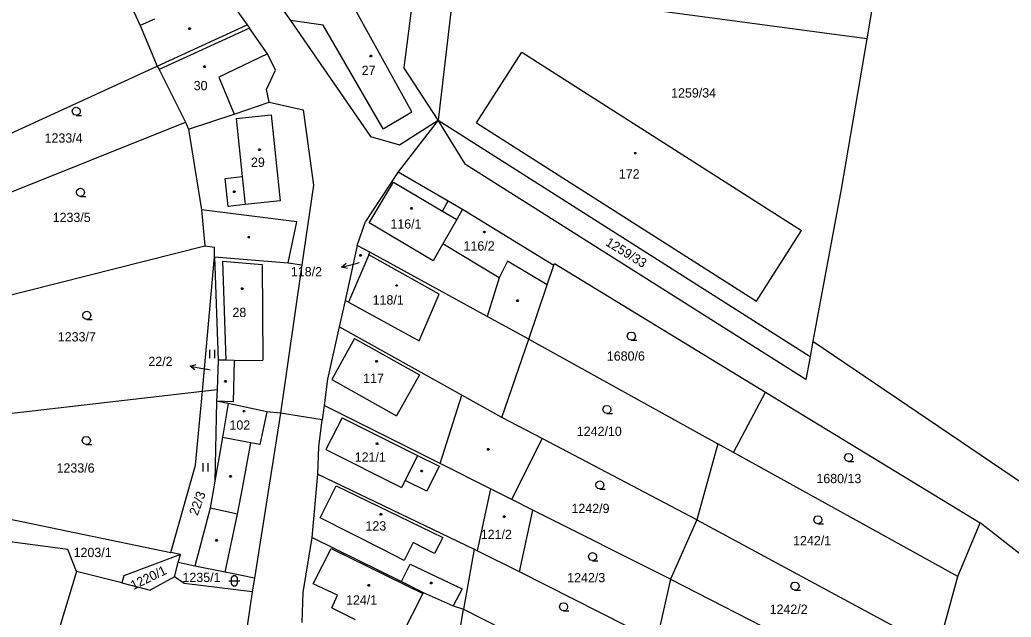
# Model space of a CAD drawing. Extents: x -802857 to -799647, y -1020285 to -1015884.
# Drawn here: x -801407 to -801225.7, y -1017994.4 to -1017885.2 of the extents above; entities that cross this region are included whole.
import ezdxf

# ---------------------------------------------------------------- set-up
doc = ezdxf.new("R2010")
doc.units = 0
for name, color, linetype in [('Default', 7, 'Continuous'), ('KN_HRANICE', 7, 'Continuous'), ('KN_KULTURY', 7, 'Continuous'), ('KN_PARCELY', 7, 'Continuous'), ('KN_SLUCKY', 7, 'Continuous')]:
    doc.layers.add(name, color=color, linetype=linetype)

# ---------------------------------------------------------------- blocks, each defined once
blk = doc.blocks.new('304')
at = {"layer": 'Default'}
blk.add_lwpolyline([(0, 0), (-0.38, 0.1), (-0.65, 0.37), (-0.75, 0.74), (-0.65, 1.11), (-0.38, 1.38), (-0.01, 1.48), (0.36, 1.38), (0.63, 1.11), (0.73, 0.73), (0.63, 0.35), (0.36, 0.08), (-0.02, -0.02), (0.98, -0.02)], dxfattribs=at)
blk = doc.blocks.new('306')
at = {"layer": 'Default'}
for p, q in [((-0.5, 1.5), (-0.5, 0)), ((0.5, 0), (0.5, 1.5))]:
    blk.add_line(p, q, dxfattribs=at)
blk = doc.blocks.new('316')
at = {"layer": 'Default'}
for points in [[(-0.5, 1.5), (-0.4, 1.79), (-0.15, 1.97), (0.16, 1.97), (0.41, 1.79), (0.51, 1.5), (0.51, 0.5), (0.41, 0.21), (0.16, 0.03), (-0.15, 0.03), (-0.4, 0.21), (-0.5, 0.5), (-0.5, 1.5)], [(-1, 1), (0.27, 1), (1, 1)]]:
    blk.add_lwpolyline(points, dxfattribs=at)
blk = doc.blocks.new('NAHRADNI_SYMBOL')
at = {"layer": 'Default'}
blk.add_lwpolyline([(0.09, 0.15), (0.18, 0), (0.09, -0.15), (-0.09, -0.15), (-0.18, 0), (-0.09, 0.15), (0.09, 0.15)], dxfattribs=at)
blk = doc.blocks.new('10292')
at = {"layer": 'Default'}
blk.add_line((0, 3), (0, 0), dxfattribs=at)
blk.add_lwpolyline([(-0.5, 2), (0, 3), (0.5, 2)], dxfattribs=at)
blk = doc.blocks.new('402')
at = {"layer": 'Default'}
blk.add_lwpolyline([(0.09, 0.15), (0.18, 0), (0.09, -0.15), (-0.09, -0.15), (-0.18, 0), (-0.09, 0.15), (0.09, 0.15)], dxfattribs=at)

msp = doc.modelspace()

# ---------------------------------------------------------------- linework, layer by layer
at = {"layer": 'KN_HRANICE'}
for p, q in [((-801333.53, -1017868.36), (-801336.82, -1017893.87)), ((-801249.45, -1017873.01), (-801252.11, -1017888.65)), ((-801327.56, -1017878.51), (-801330.54, -1017903.51)), ((-801252.11, -1017888.65), (-801327.56, -1017878.51)), ((-801387.94, -1017879.91), (-801384.99, -1017886.23)), ((-801370.22, -1017879.44), (-801365.46, -1017886.06)), ((-801358.71, -1017883.58), (-801357.53, -1017885.3)), ((-801384.99, -1017886.23), (-801381.92, -1017893.65)), ((-801365.46, -1017886.06), (-801365.03, -1017886.71)), ((-801357.53, -1017885.3), (-801342.89, -1017906.53)), ((-801365.03, -1017886.71), (-801381.54, -1017894.26)), ((-801361.74, -1017891.36), (-801365.03, -1017886.71)), ((-801252.11, -1017888.65), (-801256.79, -1017916.12)), ((-801360.26, -1017894.37), (-801361.74, -1017891.36)), ((-801323.48, -1017904.01), (-801315.22, -1017891.06)), ((-801315.22, -1017891.06), (-801264.04, -1017923.7)), ((-801414.45, -1017908.61), (-801381.92, -1017893.65)), ((-801381.92, -1017893.65), (-801381.54, -1017894.26)), ((-801381.54, -1017894.26), (-801376.7, -1017903.9)), ((-801361.91, -1017897.94), (-801360.26, -1017894.37)), ((-801330.54, -1017903.51), (-801336.82, -1017893.87)), ((-801361.41, -1017900.25), (-801361.91, -1017897.94)), ((-801367.85, -1017902.42), (-801361.41, -1017900.25)), ((-801361.41, -1017900.25), (-801355.21, -1017901.66)), ((-801376.18, -1017905.18), (-801367.85, -1017902.42)), ((-801355.21, -1017901.66), (-801353.31, -1017915.4)), ((-801416.02, -1017919.61), (-801376.7, -1017903.9)), ((-801376.7, -1017903.9), (-801376.18, -1017905.18)), ((-801330.54, -1017903.51), (-801337.83, -1017912.98)), ((-801337.61, -1017908.03), (-801330.54, -1017903.51)), ((-801325.53, -1017911.62), (-801330.54, -1017903.51)), ((-801330.54, -1017903.51), (-801262.48, -1017946.77)), ((-801323.48, -1017904.01), (-801272.3, -1017936.65)), ((-801376.18, -1017905.18), (-801373.8, -1017919.91)), ((-801342.89, -1017906.53), (-801337.61, -1017908.03)), ((-801263.28, -1017950.94), (-801325.53, -1017911.62)), ((-801337.83, -1017912.98), (-801343.79, -1017922.09)), ((-801337.83, -1017912.98), (-801328.66, -1017918.31)), ((-801353.31, -1017915.4), (-801355.42, -1017929.99)), ((-801256.79, -1017916.12), (-801261.98, -1017943.96)), ((-801329.74, -1017920.15), (-801328.66, -1017918.31)), ((-801328.66, -1017918.31), (-801326.07, -1017919.82)), ((-801373.8, -1017919.91), (-801373.19, -1017926.53)), ((-801329.74, -1017920.15), (-801327.1, -1017921.71)), ((-801326.07, -1017919.82), (-801309.37, -1017930.06)), ((-801345.31, -1017926.43), (-801343.79, -1017922.09)), ((-801327.1, -1017921.71), (-801329.63, -1017926.15)), ((-801272.3, -1017936.65), (-801264.04, -1017923.7)), ((-801319.36, -1017932.37), (-801329.63, -1017926.15)), ((-801417.56, -1017937.72), (-801373.19, -1017926.53)), ((-801373.19, -1017926.53), (-801371.41, -1017926.77)), ((-801371.42, -1017928.53), (-801371.41, -1017926.77)), ((-801345.31, -1017926.43), (-801347.54, -1017936.5)), ((-801343.21, -1017928.17), (-801346.9, -1017936.85)), ((-801342.99, -1017927.7), (-801345.31, -1017926.43)), ((-801343.21, -1017928.17), (-801342.99, -1017927.7)), ((-801321.54, -1017939.43), (-801342.99, -1017927.7)), ((-801373.64, -1017953.09), (-801371.42, -1017928.53)), ((-801371.42, -1017928.53), (-801357.93, -1017929.6)), ((-801371.42, -1017928.53), (-801370.74, -1017947.44)), ((-801355.42, -1017929.99), (-801359.36, -1017957.14)), ((-801357.93, -1017929.6), (-801355.42, -1017929.99)), ((-801317.8, -1017929.31), (-801319.36, -1017932.37)), ((-801310.57, -1017933.62), (-801317.8, -1017929.31)), ((-801309.37, -1017930.06), (-801309.25, -1017929.73)), ((-801309.25, -1017929.73), (-801270.61, -1017953.27)), ((-801310.57, -1017933.62), (-801309.37, -1017930.06)), ((-801313.94, -1017943.59), (-801310.57, -1017933.62)), ((-801347.54, -1017936.5), (-801348.61, -1017941.32)), ((-801346.9, -1017936.85), (-801347.54, -1017936.5)), ((-801313.94, -1017943.59), (-801321.54, -1017939.43)), ((-801348.61, -1017941.32), (-801350.73, -1017950.9)), ((-801326.17, -1017953.84), (-801348.61, -1017941.32)), ((-801318.88, -1017957.91), (-801313.94, -1017943.59)), ((-801313.94, -1017943.59), (-801279.37, -1017962.72)), ((-801261.98, -1017943.96), (-801262.48, -1017946.77)), ((-801261.98, -1017943.96), (-801198.39, -1017987.04)), ((-801370.74, -1017947.44), (-801370.95, -1017952.78)), ((-801262.55, -1017947.15), (-801263.28, -1017950.94)), ((-801262.48, -1017946.77), (-801262.55, -1017947.15)), ((-801350.73, -1017950.9), (-801351.38, -1017955.73)), ((-801419.31, -1017958.41), (-801373.64, -1017953.09)), ((-801374.87, -1017966.64), (-801373.64, -1017953.09)), ((-801373.64, -1017953.09), (-801370.95, -1017952.78)), ((-801370.95, -1017952.78), (-801371.03, -1017954.93)), ((-801276.5, -1017964.31), (-801270.61, -1017953.27)), ((-801270.61, -1017953.27), (-801231.39, -1017977.16)), ((-801371.03, -1017954.93), (-801371.36, -1017969.59)), ((-801368.92, -1017955.35), (-801371.03, -1017954.93)), ((-801361.84, -1017956.87), (-801368.92, -1017955.35)), ((-801318.88, -1017957.91), (-801326.17, -1017953.84)), ((-801359.36, -1017957.14), (-801364.13, -1017987.34)), ((-801359.36, -1017957.14), (-801361.84, -1017956.87)), ((-801351.73, -1017958.32), (-801359.36, -1017957.14)), ((-801351.38, -1017955.73), (-801351.73, -1017958.32)), ((-801330.17, -1017966.36), (-801351.38, -1017955.73)), ((-801352.32, -1017963.31), (-801351.73, -1017958.32)), ((-801311.5, -1017961.78), (-801318.88, -1017957.91)), ((-801317.05, -1017972.94), (-801311.5, -1017961.78)), ((-801283.17, -1017976.65), (-801311.5, -1017961.78)), ((-801352.51, -1017968.31), (-801352.32, -1017963.31)), ((-801279.37, -1017962.72), (-801283.17, -1017976.65)), ((-801276.5, -1017964.31), (-801279.37, -1017962.72)), ((-801235.44, -1017987.03), (-801276.5, -1017964.31)), ((-801379.38, -1017982.63), (-801374.87, -1017966.64)), ((-801320.94, -1017970.99), (-801330.17, -1017966.36)), ((-801371.36, -1017969.59), (-801372.21, -1017974.52)), ((-801353.58, -1017979.89), (-801352.51, -1017968.31)), ((-801352.51, -1017968.31), (-801323.93, -1017982)), ((-801320.94, -1017970.99), (-801323.35, -1017982.29)), ((-801317.05, -1017972.94), (-801320.94, -1017970.99)), ((-801313.17, -1017974.89), (-801317.05, -1017972.94)), ((-801420.83, -1017974.05), (-801379.38, -1017982.63)), ((-801372.21, -1017974.52), (-801375.02, -1017985.09)), ((-801315.64, -1017986.18), (-801313.17, -1017974.89)), ((-801288.02, -1017987.5), (-801313.17, -1017974.89)), ((-801283.17, -1017976.65), (-801288.02, -1017987.5)), ((-801283.17, -1017976.65), (-801239.16, -1018000.38)), ((-801235.44, -1017987.03), (-801231.39, -1017977.16)), ((-801209.9, -1017994.03), (-801231.39, -1017977.16)), ((-801398.22, -1017982.04), (-801421.32, -1017979.03)), ((-801355.23, -1017989.94), (-801353.58, -1017979.89)), ((-801353.58, -1017979.89), (-801337.21, -1017987.91)), ((-801396.64, -1017986.09), (-801398.22, -1017982.04)), ((-801323.93, -1017982), (-801325.88, -1017992.98)), ((-801323.35, -1017982.29), (-801323.93, -1017982)), ((-801315.64, -1017986.18), (-801323.35, -1017982.29)), ((-801377.64, -1017982.98), (-801388.03, -1017986.86)), ((-801377.64, -1017982.98), (-801379.38, -1017982.63)), ((-801378.76, -1017987.09), (-801378.04, -1017984.42)), ((-801378.04, -1017984.42), (-801377.64, -1017982.98)), ((-801375.02, -1017985.09), (-801378.04, -1017984.42)), ((-801396.64, -1017986.09), (-801403.7, -1018009.39)), ((-801388.4, -1017988.19), (-801396.64, -1017986.09)), ((-801369.47, -1017986.2), (-801375.02, -1017985.09)), ((-801364.13, -1017987.34), (-801369.47, -1017986.2)), ((-801290.6, -1017998.81), (-801315.64, -1017986.18)), ((-801388.03, -1017986.86), (-801388.4, -1017988.19)), ((-801378.76, -1017987.09), (-801383.2, -1017989.51)), ((-801376.96, -1017988.29), (-801378.76, -1017987.09)), ((-801364.13, -1017987.34), (-801364.52, -1017989.8)), ((-801337.21, -1017987.91), (-801333.24, -1017989.93)), ((-801288.02, -1017987.5), (-801290.6, -1017998.81)), ((-801288.02, -1017987.5), (-801243.96, -1018010)), ((-801239.16, -1018000.38), (-801235.44, -1017987.03)), ((-801388.4, -1017988.19), (-801383.2, -1017989.51)), ((-801364.52, -1017989.8), (-801376.96, -1017988.29)), ((-801364.52, -1017989.8), (-801366.8, -1018005.03)), ((-801355.39, -1017995.42), (-801355.23, -1017989.94)), ((-801333.24, -1017989.93), (-801327.78, -1017992.36)), ((-801327.78, -1017992.36), (-801325.88, -1017992.98)), ((-801327.78, -1018004.7), (-801325.88, -1017992.98)), ((-801325.88, -1017992.98), (-801292.85, -1018009.68))]:
    msp.add_line(p, q, dxfattribs=at)
at = {"layer": 'KN_PARCELY'}
for p, q in [((-801344.98, -1017929.64), (-801345.28, -1017929.71)), ((-801372.24, -1017949.24), (-801372.94, -1017949.1))]:
    msp.add_line(p, q, dxfattribs=at)
at = {"layer": 'KN_SLUCKY'}
for p, q in [((-801335.32, -1017902), (-801345.75, -1017883.16)), ((-801382.41, -1017885.03), (-801384.99, -1017886.23)), ((-801381.92, -1017893.65), (-801365.46, -1017886.06)), ((-801351.55, -1017886.13), (-801357.53, -1017885.3)), ((-801340.59, -1017905.11), (-801351.55, -1017886.13)), ((-801361.74, -1017891.36), (-801370.6, -1017895.68)), ((-801370.6, -1017895.68), (-801367.85, -1017902.42)), ((-801367.47, -1017903.23), (-801361.05, -1017902.52)), ((-801361.05, -1017902.52), (-801359.4, -1017918.31)), ((-801340.59, -1017905.11), (-801335.32, -1017902)), ((-801367.47, -1017903.23), (-801366.36, -1017913.86)), ((-801369.48, -1017914.19), (-801366.36, -1017913.86)), ((-801368.95, -1017919.31), (-801369.48, -1017914.19)), ((-801366.36, -1017913.86), (-801365.82, -1017918.98)), ((-801343.14, -1017922.3), (-801338.66, -1017914.88)), ((-801338.66, -1017914.88), (-801329.74, -1017920.15)), ((-801365.82, -1017918.98), (-801368.95, -1017919.31)), ((-801359.4, -1017918.31), (-801365.82, -1017918.98)), ((-801356.36, -1017922.11), (-801373.8, -1017919.91)), ((-801326.07, -1017919.82), (-801327.1, -1017921.71)), ((-801357.93, -1017929.6), (-801356.36, -1017922.11)), ((-801331.42, -1017929.24), (-801343.14, -1017922.3)), ((-801329.63, -1017926.15), (-801331.42, -1017929.24)), ((-801330.33, -1017935.36), (-801343.21, -1017928.17)), ((-801369.97, -1017929.35), (-801362.72, -1017929.9)), ((-801369.97, -1017929.35), (-801369.36, -1017947.45)), ((-801362.72, -1017929.9), (-801362.59, -1017947.45)), ((-801319.36, -1017932.37), (-801321.54, -1017939.43)), ((-801334, -1017943.9), (-801330.33, -1017935.36)), ((-801346.9, -1017936.85), (-801334, -1017943.9)), ((-801345.81, -1017943.46), (-801349.97, -1017950.96)), ((-801345.81, -1017943.46), (-801333.95, -1017950.12)), ((-801369.36, -1017947.45), (-801370.74, -1017947.44)), ((-801367.8, -1017947.47), (-801369.36, -1017947.45)), ((-801367.8, -1017947.47), (-801368.03, -1017955.07)), ((-801367.8, -1017947.47), (-801362.59, -1017947.45)), ((-801349.97, -1017950.96), (-801338.11, -1017957.62)), ((-801333.95, -1017950.12), (-801338.11, -1017957.62)), ((-801368.03, -1017955.07), (-801371.03, -1017954.93)), ((-801368.92, -1017955.35), (-801369.98, -1017961.56)), ((-801330.17, -1017966.36), (-801326.17, -1017953.84)), ((-801361.84, -1017956.87), (-801363.1, -1017962.87)), ((-801348.05, -1017957.96), (-801351.05, -1017963.8)), ((-801348.05, -1017957.96), (-801334.27, -1017964.86)), ((-801369.98, -1017961.56), (-801371.36, -1017969.59)), ((-801364.8, -1017962.55), (-801369.98, -1017961.56)), ((-801366.26, -1017970.53), (-801364.8, -1017962.55)), ((-801363.1, -1017962.87), (-801364.8, -1017962.55)), ((-801351.05, -1017963.8), (-801337.19, -1017970.74)), ((-801334.27, -1017964.86), (-801336.54, -1017969.43)), ((-801334.27, -1017964.86), (-801330.32, -1017966.84)), ((-801330.32, -1017966.84), (-801332.6, -1017971.4)), ((-801336.54, -1017969.43), (-801337.19, -1017970.74)), ((-801332.6, -1017971.4), (-801336.54, -1017969.43)), ((-801367.19, -1017975.61), (-801366.26, -1017970.53)), ((-801352.09, -1017976.3), (-801349.15, -1017970.42)), ((-801349.15, -1017970.42), (-801337.69, -1017975.98)), ((-801367.19, -1017975.61), (-801372.21, -1017974.52)), ((-801369.47, -1017986.2), (-801367.19, -1017975.61)), ((-801340.76, -1017982.03), (-801352.09, -1017976.3)), ((-801337.69, -1017975.98), (-801329.66, -1017979.87)), ((-801329.66, -1017979.87), (-801331.16, -1017982.8)), ((-801353.36, -1017988.32), (-801350.11, -1017981.87)), ((-801350.11, -1017981.87), (-801333.33, -1017990.11)), ((-801336.74, -1017984.06), (-801340.76, -1017982.03)), ((-801335.11, -1017980.8), (-801336.74, -1017984.06)), ((-801331.16, -1017982.8), (-801335.11, -1017980.8)), ((-801337.21, -1017987.91), (-801335.63, -1017984.73)), ((-801335.63, -1017984.73), (-801326.12, -1017989.25)), ((-801348.9, -1017990.41), (-801353.36, -1017988.32)), ((-801326.12, -1017989.25), (-801327.78, -1017992.36)), ((-801349.97, -1017992.75), (-801348.9, -1017990.41)), ((-801333.33, -1017990.11), (-801337.28, -1017997.9)), ((-801349.97, -1017992.75), (-801345.71, -1017994.87))]:
    msp.add_line(p, q, dxfattribs=at)

# ---------------------------------------------------------------- block references
at = {"layer": 'KN_KULTURY'}
for name, p in [('402', (-801375.99, -1017886.81)), ('402', (-801342.8, -1017891.76)), ('402', (-801373.27, -1017893.72)), ('304', (-801396.71, -1017902.64)), ('402', (-801363.17, -1017908.92)), ('402', (-801294.46, -1017909.56)), ('304', (-801395.94, -1017917.46)), ('402', (-801367.81, -1017916.59)), ('402', (-801335.39, -1017919.64)), ('402', (-801322.07, -1017924.01)), ('402', (-801365.15, -1017924.93)), ('NAHRADNI_SYMBOL', (-801344.7, -1017928.24)), ('402', (-801338.1, -1017933.77)), ('402', (-801366.36, -1017934.37)), ('402', (-801316, -1017936.53)), ('304', (-801394.78, -1017939.97)), ('304', (-801295.17, -1017943.78)), ('306', (-801371.85, -1017947.05)), ('402', (-801341.78, -1017947.62)), ('402', (-801369.42, -1017951.29)), ('402', (-801366.05, -1017956.76)), ('304', (-801299.63, -1017957.18)), ('304', (-801394.86, -1017962.85)), ('402', (-801341.68, -1017962.7)), ('402', (-801321.36, -1017963.73)), ('306', (-801373.07, -1017967.79)), ('304', (-801255.44, -1017965.97)), ('402', (-801333.53, -1017967.69)), ('402', (-801368.49, -1017968.66)), ('304', (-801300.94, -1017971)), ('402', (-801340.99, -1017975.62)), ('402', (-801318.43, -1017976.08)), ('304', (-801261.04, -1017977.36)), ('402', (-801371.04, -1017980.37)), ('304', (-801302.27, -1017984.11)), ('316', (-801367.81, -1017988.8)), ('402', (-801331.79, -1017988.17)), ('304', (-801265.24, -1017989.51)), ('402', (-801343.21, -1017988.6)), ('304', (-801307.57, -1017993.28))]:
    msp.add_blockref(name, p, dxfattribs=at)
at = {"layer": 'KN_PARCELY'}
for p, rotation in [((-801345.28, -1017929.71), 103.132403), ((-801372.94, -1017949.1), 78.667105)]:
    msp.add_blockref('10292', p, dxfattribs=dict(at, rotation=rotation))

# ---------------------------------------------------------------- texts
for s, height, p in [('27', 1.7, (-801344.51, -1017895.28)), ('30', 1.7, (-801375.23, -1017898.05)), ('1259/34', 1.7, (-801287.9, -1017899.38)), ('1233/4', 1.7, (-801402.5, -1017907.64)), ('29', 1.7, (-801364.75, -1017912.07)), ('172', 1.7, (-801297.46, -1017914.2)), ('1233/5', 1.7, (-801401.02, -1017922.16)), ('116/1', 1.7, (-801339.25, -1017923.36)), ('116/2', 1.7, (-801325.87, -1017927.38)), ('118/2', 0.1, (-801345.23, -1017929.64)), ('118/2', 1.7, (-801357.45, -1017932.09)), ('118/1', 1.7, (-801342.5, -1017937.25)), ('28', 1.7, (-801368.14, -1017939.54)), ('1233/7', 1.7, (-801400.08, -1017944.01)), ('1680/6', 1.7, (-801299.66, -1017947.52)), ('22/2', 1.7, (-801383.52, -1017948.51)), ('22/2', 0.1, (-801372.44, -1017949.24)), ('117', 1.7, (-801344.23, -1017951.58)), ('102', 1.7, (-801368.68, -1017960.15)), ('1242/10', 1.7, (-801305.15, -1017961.29)), ('121/1', 1.7, (-801345.78, -1017966.01)), ('1233/6', 1.7, (-801400.31, -1017968)), ('1680/13', 1.7, (-801261.33, -1017969.93)), ('1242/9', 1.7, (-801306.13, -1017975.41)), ('123', 1.7, (-801343.81, -1017978.6)), ('121/2', 1.7, (-801322.72, -1017980.16)), ('1242/1', 1.7, (-801265.59, -1017981.29)), ('1203/1', 1.7, (-801397.19, -1017983.46)), ('1235/1', 1.7, (-801377.28, -1017988.02)), ('1242/3', 1.7, (-801306.91, -1017988.07)), ('124/1', 1.7, (-801347.36, -1017992.15)), ('1242/2', 1.7, (-801269.88, -1017993.84))]:
    msp.add_text(s, height=height, dxfattribs=at).set_placement(p)
for s, rotation, p in [('1259/33', 328.591, (-801300.05, -1017926.32)), ('22/3', 70.015, (-801374.52, -1017975.98)), ('1220/1', 25.783, (-801386.28, -1017989.5))]:
    msp.add_text(s, height=1.7, rotation=rotation, dxfattribs=at).set_placement(p)

doc.saveas('drawing.dxf')
